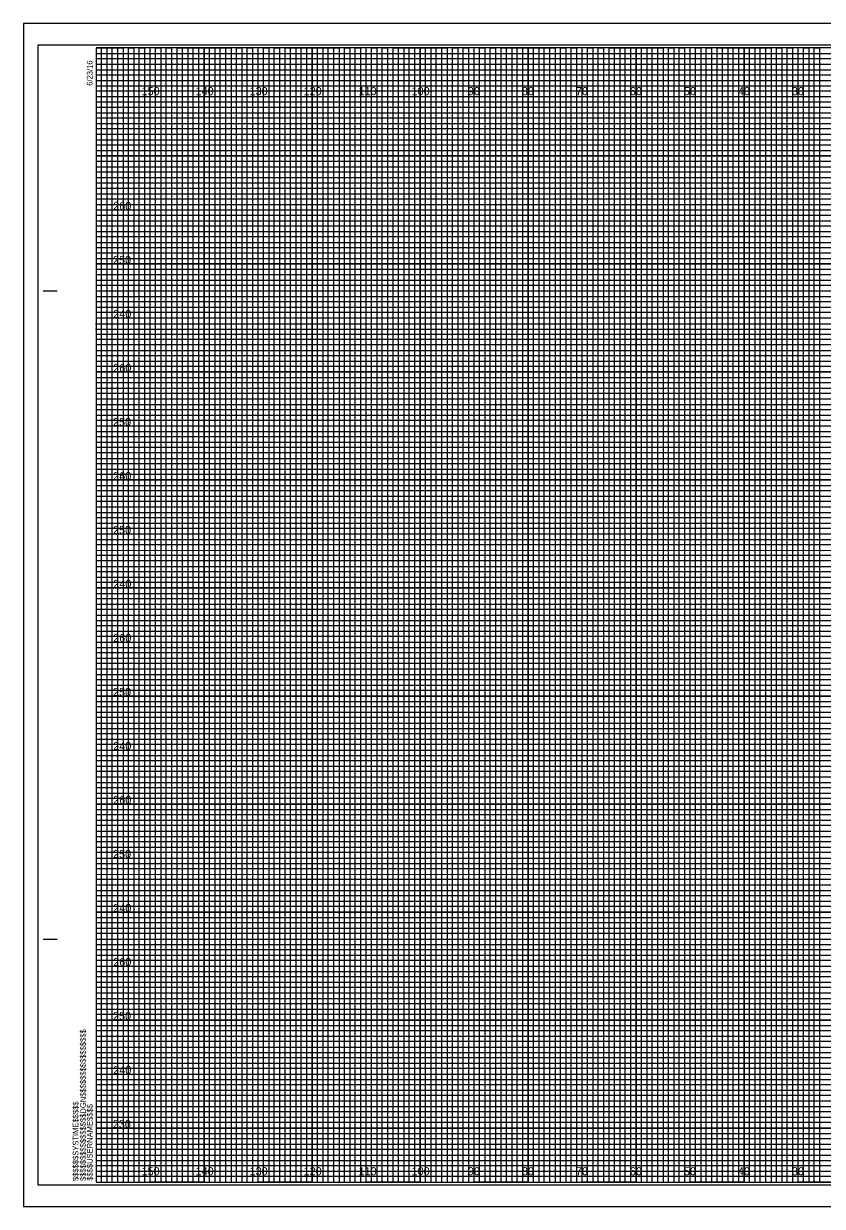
# Model space of a CAD drawing. Extents: x -13 to 359, y -5 to 2854.
# Drawn here: x -13.4 to 134.5, y 2415.5 to 2634.5 of the extents above; entities that cross this region are included whole.
import ezdxf

# ---------------------------------------------------------------- set-up
doc = ezdxf.new("R2010")
doc.units = 0
for name, color, linetype in [('Exist Cross Section Cell', 7, 'Continuous'), ('Exist XS Ground Line', 7, 'Continuous'), ('Prop CMT Concrete Structures', 7, 'Continuous'), ('Prop CMT DNC', 7, 'Continuous'), ('Prop CMT Pvmt Course 1', 7, 'Continuous'), ('Prop CMT Pvmt Course 1 CG', 7, 'Continuous'), ('Prop CMT Pvmt Course 2', 7, 'Continuous'), ('Prop CMT Shear Line', 7, 'Continuous'), ('Prop CMT Slope Grass', 7, 'Continuous'), ('Prop CMT Subgrade Earthwork', 7, 'Continuous'), ('Scratch_Level_0', 7, 'Continuous')]:
    doc.layers.add(name, color=color, linetype=linetype)

msp = doc.modelspace()

# ---------------------------------------------------------------- linework, layer by layer
at = {"layer": 'Exist XS Ground Line'}
for p, q in [((10, 2630), (0, 2630)), ((10, 2420), (10, 2630)), ((30, 2630), (20, 2630)), ((20, 2630), (20, 2420)), ((30, 2420), (30, 2630)), ((50, 2630), (40, 2630)), ((40, 2630), (40, 2420)), ((50, 2420), (50, 2630)), ((70, 2630), (60, 2630)), ((60, 2630), (60, 2420)), ((70, 2420), (70, 2630)), ((90, 2630), (80, 2630)), ((80, 2630), (80, 2420)), ((90, 2420), (90, 2630)), ((110, 2630), (100, 2630)), ((100, 2630), (100, 2420)), ((110, 2420), (110, 2630)), ((130, 2630), (120, 2630)), ((120, 2630), (120, 2420)), ((130, 2420), (130, 2630)), ((20, 2420), (10, 2420)), ((40, 2420), (30, 2420)), ((60, 2420), (50, 2420)), ((80, 2420), (70, 2420)), ((100, 2420), (90, 2420)), ((120, 2420), (110, 2420)), ((140, 2420), (130, 2420))]:
    msp.add_line(p, q, dxfattribs=at)
for points in [[(0, 2620), (320, 2620), (320, 2610), (0, 2610)], [(0, 2600), (320, 2600), (320, 2590), (0, 2590)], [(0, 2580), (320, 2580), (320, 2570), (0, 2570)], [(0, 2560), (320, 2560), (320, 2550), (0, 2550)], [(0, 2540), (320, 2540), (320, 2530), (0, 2530)], [(0, 2520), (320, 2520), (320, 2510), (0, 2510)], [(0, 2500), (320, 2500), (320, 2490), (0, 2490)], [(0, 2480), (320, 2480), (320, 2470), (0, 2470)], [(0, 2460), (320, 2460), (320, 2450), (0, 2450)], [(0, 2440), (320, 2440), (320, 2430), (0, 2430)]]:
    msp.add_lwpolyline(points, dxfattribs=at)
at = {"layer": 'Prop CMT Concrete Structures'}
for p, q in [((-9.8, 2585), (-7.3, 2585)), ((-9.7, 2585), (-7.2, 2585)), ((-9.8, 2465), (-7.3, 2465)), ((-9.7, 2465), (-7.2, 2465)), ((0, 2420), (0, 2420)), ((0, 2420), (0, 2420)), ((0, 2420), (0, 2420)), ((0, 2420), (0, 2420)), ((0, 2420), (0, 2420)), ((0, 2420), (0, 2420)), ((0, 2420), (0, 2420))]:
    msp.add_line(p, q, dxfattribs=at)
msp.add_lwpolyline([(320, 2630), (0, 2630), (0, 2420), (320, 2420)], close=True, dxfattribs=at)
at = {"layer": 'Prop CMT DNC'}
for p, q in [((323.3, 2634.5), (-13.4, 2634.5)), ((-13.4, 2634.5), (-13.4, 2415.5)), ((-13.4, 2415.5), (323.3, 2415.5))]:
    msp.add_line(p, q, dxfattribs=at)
at = {"layer": 'Prop CMT Pvmt Course 1'}
for p, q in [((0, 2629), (260, 2629)), ((260, 2627.98), (0, 2627.98)), ((0, 2627.98), (0, 2627)), ((0, 2627), (260, 2627)), ((260, 2625.89), (0, 2625.89)), ((0, 2625.89), (0, 2624)), ((0, 2624), (320, 2624))]:
    msp.add_line(p, q, dxfattribs=at)
for points in [[(0, 2623), (270, 2623), (320, 2623), (320, 2622), (0, 2622)], [(0, 2621), (320, 2621), (320, 2619), (0, 2619)], [(0, 2618), (320, 2618), (320, 2617), (0, 2616.98)], [(0, 2616), (320, 2616), (320, 2614), (0, 2614)], [(0, 2613), (320, 2613), (320, 2612), (0, 2612)], [(0, 2611), (320, 2611), (320, 2609), (0, 2609)], [(0, 2608), (320, 2608), (320, 2607), (0, 2607)], [(0, 2606), (320, 2606), (320, 2604), (0, 2604)], [(0, 2603), (320, 2603), (320, 2602), (0, 2602)], [(0, 2601), (320, 2601), (320, 2599), (0, 2599)], [(0, 2598), (320, 2598), (320, 2597), (0, 2597)], [(0, 2596), (320, 2596), (320, 2593.95), (320, 2593), (320, 2592), (0, 2592)], [(0, 2594), (320, 2594), (320, 2593), (0, 2593)], [(0, 2591), (320, 2591), (320, 2589), (0, 2589.03)], [(0, 2589.03), (320, 2589), (320, 2588), (0, 2588)], [(0, 2587), (320, 2587), (320, 2586), (0, 2586)], [(0, 2584), (320, 2584), (320, 2583), (0, 2583)], [(0, 2582), (320, 2582), (320, 2581), (0, 2581)], [(-0.07, 2578.89), (320, 2578.89), (320, 2577.88), (-0.07, 2577.88)], [(0, 2577), (320, 2577), (320, 2576), (0, 2576)], [(0, 2574), (320, 2574), (320, 2573), (0, 2573)], [(0, 2572), (320, 2572), (320, 2571), (0, 2571)], [(0, 2569), (320, 2569), (320, 2568), (0, 2568)], [(0, 2567), (320, 2567), (320, 2566), (0, 2566)], [(0, 2564), (320, 2564), (320, 2563), (0, 2563)], [(0, 2562), (320, 2562), (320, 2561), (0, 2561)], [(0, 2559), (320, 2559), (319.99, 2557.98), (0, 2558)], [(0, 2557), (320, 2557), (320, 2556), (0, 2556)], [(0, 2554), (320, 2554), (320, 2553), (0, 2553)], [(0, 2552), (320, 2552), (320, 2551), (0, 2551)], [(0, 2549), (320, 2549), (320, 2548), (0, 2548)], [(0, 2547), (320, 2547), (320, 2546), (0, 2546)], [(0, 2544), (320, 2544), (320, 2543), (0, 2543)], [(0, 2542), (320, 2542), (320, 2541), (0, 2541)], [(0, 2539), (320, 2539), (320, 2538), (0, 2538)], [(0, 2536.99), (320.07, 2536.91), (320, 2536), (0, 2536)], [(0, 2534), (320, 2534), (320, 2533), (0, 2533)], [(0, 2532), (320, 2532), (320, 2531), (0, 2531)], [(0, 2529), (320, 2529), (320, 2528), (0, 2528)], [(0, 2527), (320, 2527), (320, 2526), (0, 2526)], [(0, 2524), (320, 2524), (320, 2523), (0, 2523)], [(0, 2522), (320, 2522), (320, 2521), (0, 2521)], [(0, 2519), (320, 2519), (320, 2518), (0, 2518)], [(0, 2517), (320, 2517), (320, 2516), (0, 2516)], [(0, 2514), (320, 2514), (320, 2513), (0, 2513)], [(0, 2512), (320, 2512), (320, 2511), (0, 2511)], [(0, 2509), (320, 2509), (320, 2508), (0, 2508)], [(0, 2507), (320, 2507), (320, 2506), (0, 2506)], [(0, 2504), (320, 2504), (320, 2503), (0, 2503)], [(0, 2502), (320, 2502), (320, 2501), (0, 2501)], [(0, 2499), (320, 2499), (319.99, 2497.98), (0, 2498)], [(0, 2497), (320, 2497), (320, 2496), (0, 2496)], [(0, 2494), (320, 2494), (320, 2493), (0, 2493)], [(0, 2492), (320, 2492), (320, 2491), (0, 2491)], [(0, 2489), (320, 2489), (320, 2488), (0, 2488)], [(0, 2487), (320, 2487), (320, 2486), (0, 2486)], [(0, 2484), (320, 2484), (320, 2483), (0, 2483)], [(0, 2482), (320, 2482), (320, 2481), (0, 2481)], [(0, 2479), (320, 2479), (320, 2478), (0, 2478)], [(0, 2476.99), (320.07, 2476.91), (320, 2476), (0, 2476)], [(0, 2474), (320, 2474), (320, 2473), (0, 2473)], [(0, 2472), (320, 2472), (320, 2471), (0, 2471)], [(0, 2469), (320, 2469), (320, 2468), (0, 2468)], [(0, 2467), (320, 2467), (320, 2466), (0, 2466)], [(0, 2464), (320, 2464), (320, 2463), (0, 2463)], [(0, 2462), (320, 2462), (320, 2461), (0, 2461)], [(0, 2459), (320, 2459), (320, 2458), (0, 2458)], [(0, 2457), (320, 2457), (320, 2456), (0, 2456)], [(0, 2454), (320, 2454), (320, 2453), (0, 2453)], [(0, 2452), (320, 2452), (320, 2451), (0, 2451)], [(0, 2449), (320, 2449), (320, 2448), (0, 2448)], [(0, 2447), (320, 2447), (320, 2446), (0, 2446)], [(0, 2444), (320, 2444), (320, 2443), (0, 2443)], [(0, 2442), (320, 2442), (320, 2441), (0, 2441)], [(0, 2439), (320, 2439), (320, 2438), (0, 2438)], [(0, 2437), (320, 2437), (320, 2436), (0, 2436)], [(0, 2434), (320, 2434), (320, 2433), (0, 2433)], [(0, 2432), (320, 2432), (320, 2431), (0, 2431)], [(0, 2429), (320, 2429), (320, 2428), (0, 2428)], [(0, 2427), (320, 2427), (320, 2426), (0, 2426)], [(0, 2424), (320, 2424), (320, 2423), (0, 2423)], [(0, 2422), (320, 2422), (320, 2421), (0, 2421)]]:
    msp.add_lwpolyline(points, dxfattribs=at)
at = {"layer": 'Prop CMT Pvmt Course 1 CG'}
for points in [[(0, 2420), (1, 2420), (1, 2630), (2, 2630), (2, 2420)], [(2, 2420), (3, 2420), (3, 2630), (4, 2630), (4, 2420)], [(5, 2420), (6, 2420), (6, 2630), (7, 2630), (7, 2420)], [(7, 2420), (8, 2420), (8, 2630), (9, 2630), (9, 2420)], [(10, 2420), (11, 2420), (11, 2630), (12, 2630), (12, 2420)], [(12, 2420), (13, 2420), (13, 2630), (14, 2630), (14, 2420)], [(15, 2420), (16, 2420), (16, 2630), (17, 2630), (17, 2420)], [(17, 2420), (18, 2420), (18, 2630), (19, 2630), (19, 2420)], [(20, 2420), (21, 2420), (21, 2630), (22, 2630), (22, 2420)], [(22, 2420), (23, 2420), (23, 2630), (24, 2630), (24, 2420)], [(25, 2420), (26, 2420), (26, 2630), (27, 2630), (27, 2420)], [(27, 2420), (28, 2420), (28, 2630), (29, 2630), (29, 2420)], [(30, 2420), (31, 2420), (31, 2630), (32, 2630), (32, 2420)], [(32, 2420), (33, 2420), (33, 2630), (34, 2630), (34, 2420)], [(35, 2420), (36, 2420), (36, 2630), (37, 2630), (37, 2420)], [(37, 2420), (38, 2420), (38, 2630), (39, 2630), (39, 2420)], [(40, 2420), (41, 2420), (41, 2630), (42, 2630), (42, 2420)], [(42, 2420), (43, 2420), (43, 2630), (44, 2630), (44, 2420)], [(45, 2420), (46, 2420), (46, 2630), (47, 2630), (47, 2420)], [(47, 2420), (48, 2420), (48, 2630), (49, 2630), (49, 2420)], [(50, 2420), (51, 2420), (51, 2630), (52, 2630), (52, 2420)], [(52, 2420), (53, 2420), (53, 2630), (54, 2630), (54, 2420)], [(55, 2420), (56, 2420), (56, 2630), (57, 2630), (57, 2420)], [(57, 2420), (58, 2420), (58, 2630), (59, 2630), (59, 2420)], [(60, 2420), (61, 2420), (61, 2630), (62, 2630), (62, 2420)], [(62, 2420), (63, 2420), (63, 2630), (64, 2630), (64, 2420)], [(65, 2420), (66, 2420), (66, 2630), (67, 2630), (67, 2420)], [(67, 2420), (68, 2420), (68, 2630), (69, 2630), (69, 2420)], [(70, 2420), (71, 2420), (71, 2630), (72, 2630), (72, 2420)], [(72, 2420), (73, 2420), (73, 2630), (74, 2630), (74, 2420)], [(75, 2420), (76, 2420), (76, 2630), (77, 2630), (77, 2420)], [(77, 2420), (78, 2420), (78, 2630), (79, 2630), (79, 2420)], [(80, 2420), (81, 2420), (81, 2630), (82, 2630), (82, 2420)], [(82, 2420), (83, 2420), (83, 2630), (84, 2630), (84, 2420)], [(85, 2420), (86, 2420), (86, 2630), (87, 2630), (87, 2420)], [(87, 2420), (88, 2420), (88, 2630), (89, 2630), (89, 2420)], [(90, 2420), (91, 2420), (91, 2630), (92, 2630), (92, 2420)], [(92, 2420), (93, 2420), (93, 2630), (94, 2630), (94, 2420)], [(95, 2420), (96, 2420), (96, 2630), (97, 2630), (97, 2420)], [(97, 2420), (98, 2420), (98, 2630), (99, 2630), (99, 2420)], [(100, 2420), (101, 2420), (101, 2630), (102, 2630), (102, 2420)], [(102, 2420), (103, 2420), (103, 2630), (104, 2630), (104, 2420)], [(105, 2420), (106, 2420), (106, 2630), (107, 2630), (107, 2420)], [(107, 2420), (108, 2420), (108, 2630), (109, 2630), (109, 2420)], [(110, 2420), (111, 2420), (111, 2630), (112, 2630), (112, 2420)], [(112, 2420), (113, 2420), (113, 2630), (114, 2630), (114, 2420)], [(115, 2420), (116, 2420), (116, 2630), (117, 2630), (117, 2420)], [(117, 2420), (118, 2420), (118, 2630), (119, 2630), (119, 2420)], [(120, 2420), (121, 2420), (121, 2630), (122, 2630), (122, 2420)], [(122, 2420), (123, 2420), (123, 2630), (124, 2630), (124, 2420)], [(125, 2420), (126, 2420), (126, 2630), (127, 2630), (127, 2420)], [(127, 2420), (128, 2420), (128, 2630), (129, 2630), (129, 2420)], [(130, 2420), (131, 2420), (131, 2630), (132, 2630), (132, 2420)], [(132, 2420), (133, 2420), (133, 2630), (134, 2630), (134, 2420)]]:
    msp.add_lwpolyline(points, dxfattribs=at)
at = {"layer": 'Prop CMT Shear Line'}
for p, q in [((10, 2420), (10, 2630)), ((20, 2420), (20, 2630)), ((30, 2420), (30, 2630)), ((40, 2420), (40, 2630)), ((50, 2420), (50, 2630)), ((60, 2420), (60, 2630)), ((70, 2420), (70, 2630)), ((80, 2420), (80, 2630)), ((90, 2420), (90, 2630)), ((100, 2420), (100, 2630)), ((110, 2420), (110, 2630)), ((120, 2420), (120, 2630)), ((130, 2420), (130, 2630)), ((0, 2620), (320, 2620)), ((0, 2610), (320, 2610)), ((0, 2600), (320, 2600)), ((0, 2590), (320, 2590)), ((0, 2580), (320, 2580)), ((0, 2570), (320, 2570)), ((0, 2560), (320, 2560)), ((0, 2550), (320, 2550)), ((0, 2540), (320, 2540)), ((0, 2530), (320, 2530)), ((0, 2520), (320, 2520)), ((0, 2510), (320, 2510)), ((0, 2500), (320, 2500)), ((0, 2490), (320, 2490)), ((0, 2480), (320, 2480)), ((0, 2470), (320, 2470)), ((0, 2460), (320, 2460)), ((0, 2450), (320, 2450)), ((0, 2440), (320, 2440)), ((0, 2430), (320, 2430))]:
    msp.add_line(p, q, dxfattribs=at)
at = {"layer": 'Prop CMT Slope Grass'}
msp.add_lwpolyline([(-10.8, 2419.5), (322.4, 2419.5), (322.4, 2630.5), (-10.8, 2630.5)], close=True, dxfattribs=at)
at = {"layer": 'Prop CMT Subgrade Earthwork'}
msp.add_lwpolyline([(-13.4, 2415.5), (323.3, 2415.5), (323.3, 2634.5), (-13.4, 2634.5)], close=True, dxfattribs=at)
at = {"layer": 'Scratch_Level_0'}
for points in [[(0, 2630), (5, 2630), (5, 2420), (15, 2420), (15, 2630), (25, 2630), (25, 2420), (35, 2420), (35, 2630), (45, 2630), (45, 2420), (55, 2420), (55, 2630), (65, 2630), (65, 2420), (75, 2420), (75, 2630), (85, 2630), (85, 2420), (95, 2420), (95, 2630), (105, 2630), (105, 2420), (115, 2420), (115, 2630), (125, 2630), (125, 2420), (135, 2420)], [(0, 2625), (275, 2625)], [(0, 2605), (320, 2605), (320, 2615), (0, 2615)], [(0, 2585), (320, 2585), (320, 2595), (0, 2595)], [(0, 2565), (320, 2565), (320, 2575), (0, 2575)], [(0, 2545), (320, 2545), (320, 2555), (0, 2555)], [(0, 2525), (320, 2525), (320, 2535), (0, 2535)], [(0, 2505), (320, 2505), (320, 2515), (0, 2515)], [(0, 2485), (320, 2485), (320, 2495), (0, 2495)], [(0, 2465), (320, 2465), (320, 2475), (0, 2475)], [(0, 2445), (320, 2445), (320, 2455), (0, 2455)], [(0, 2425), (320, 2425), (320, 2435), (0, 2435)]]:
    msp.add_lwpolyline(points, dxfattribs=at)

# ---------------------------------------------------------------- texts
at = {"layer": 'Exist Cross Section Cell'}
for s, p in [('150', (8.44, 2621.25)), ('140', (18.44, 2621.25)), ('130', (28.44, 2621.25)), ('120', (38.44, 2621.25)), ('110', (48.62, 2621.25)), ('100', (58.44, 2621.25)), ('90', (68.86, 2621.25)), ('80', (78.86, 2621.25)), ('70', (88.86, 2621.25)), ('60', (98.86, 2621.25)), ('50', (108.86, 2621.25)), ('40', (118.86, 2621.25)), ('30', (128.86, 2621.25)), ('150', (8.44, 2421.25)), ('140', (18.44, 2421.25)), ('130', (28.44, 2421.25)), ('120', (38.44, 2421.25)), ('110', (48.62, 2421.25)), ('100', (58.44, 2421.25)), ('90', (68.86, 2421.25)), ('80', (78.86, 2421.25)), ('70', (88.86, 2421.25)), ('60', (98.86, 2421.25)), ('50', (108.86, 2421.25)), ('40', (118.86, 2421.25)), ('30', (128.86, 2421.25))]:
    msp.add_text(s, height=1.5, dxfattribs=at).set_placement(p)
at = {"layer": 'Prop CMT Concrete Structures'}
for s, p in [('6/23/16', (-0.65, 2623)), ('$$$$$$$$$$$$$$$$DGN$$$$$$$$$$$$$$$$', (-1.88, 2420.18)), ('$$$$$$SYSTIME$$$$$', (-3.26, 2420.18)), ('$$$$USERNAME$$$$', (-0.62, 2420.23))]:
    msp.add_text(s, height=1.05, rotation=90, dxfattribs=at).set_placement(p)
at = {"layer": 'Prop CMT Pvmt Course 2'}
for s, p in [('260', (3.19, 2600)), ('250', (3.15, 2590)), ('240', (3.19, 2580)), ('260', (3.19, 2570)), ('250', (3.15, 2560)), ('260', (3.19, 2550)), ('240', (3.19, 2550)), ('250', (3.15, 2540)), ('240', (3.19, 2530)), ('260', (3.19, 2520)), ('250', (3.15, 2510)), ('240', (3.19, 2500)), ('260', (3.19, 2490)), ('250', (3.15, 2480)), ('240', (3.19, 2470)), ('260', (3.19, 2460)), ('250', (3.15, 2450)), ('240', (3.19, 2440)), ('230', (3.11, 2430))]:
    msp.add_text(s, height=1.5, dxfattribs=at).set_placement(p)

doc.saveas('drawing.dxf')
